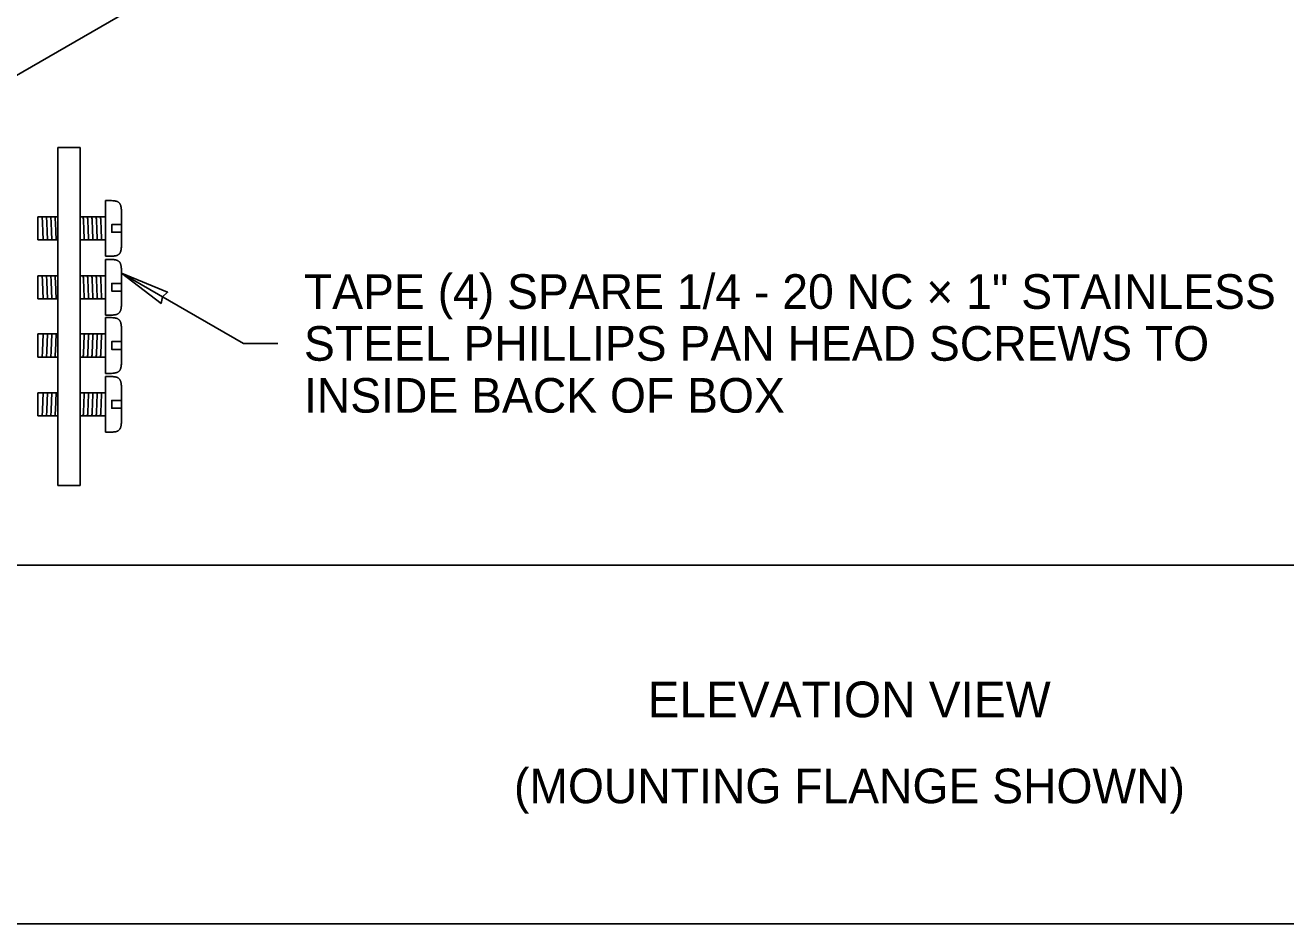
# Model space of a CAD drawing. Extents: x 99862 to 104211, y 98939 to 102076.
# Drawn here: x 100754 to 101337, y 100000 to 100415 of the extents above; entities that cross this region are included whole.
import ezdxf

# ---------------------------------------------------------------- set-up
doc = ezdxf.new("R2010")
doc.units = 0
for name, color, linetype in [('Level 1', 7, 'Continuous'), ('Level 15', 7, 'Continuous'), ('Level 20', 7, 'Continuous'), ('Level 3', 7, 'Continuous'), ('Level 4', 7, 'Continuous')]:
    doc.layers.add(name, color=color, linetype=linetype)

msp = doc.modelspace()

# ---------------------------------------------------------------- linework, layer by layer
at = {"layer": 'Level 1'}
for p, q in [((100768.9, 100202.13), (100768.9, 100358.41)), ((100768.9, 100358.41), (100779.31, 100358.41)), ((100779.31, 100358.41), (100779.31, 100202.13)), ((100779.31, 100202.13), (100768.9, 100202.13)), ((100779.31, 100202.13), (100779.31, 100202.13)), ((101689.83, 100165.23), (100609.83, 100165.23))]:
    msp.add_line(p, q, dxfattribs=at)
msp.add_lwpolyline([(99862, 99999.5), (103151, 99999.5), (103151, 102075.5), (99862, 102075.5)], close=True, dxfattribs=at)
at = {"layer": 'Level 15'}
for p, q in [((100587.71, 100298.08), (100839.76, 100443.6)), ((100798.43, 100300.26), (100854.72, 100267.76)), ((100854.72, 100267.76), (100870.72, 100267.76))]:
    msp.add_line(p, q, dxfattribs=at)
msp.add_lwpolyline([(100798.44, 100300.26), (100816.71, 100286.26), (100817.29, 100289.37), (100819.7, 100291.43)], close=True, dxfattribs=at)
at = {"layer": 'Level 3'}
for p, q in [((100790.94, 100308.03), (100790.94, 100333.82)), ((100768.9, 100326.27), (100759.66, 100326.27)), ((100759.66, 100326.27), (100759.66, 100315.59)), ((100790.94, 100326.27), (100779.42, 100326.27)), ((100798.44, 100327.47), (100798.44, 100314.39)), ((100759.66, 100315.59), (100768.9, 100315.59)), ((100790.94, 100315.59), (100779.42, 100315.59)), ((100790.94, 100280.82), (100790.94, 100306.61)), ((100768.9, 100299.06), (100759.66, 100299.06)), ((100759.66, 100299.06), (100759.66, 100288.38)), ((100790.94, 100299.06), (100779.42, 100299.06)), ((100798.44, 100300.26), (100798.44, 100287.18)), ((100759.66, 100288.38), (100768.9, 100288.38)), ((100779.42, 100288.38), (100790.94, 100288.38)), ((100790.94, 100253.92), (100790.94, 100279.71)), ((100768.9, 100272.16), (100759.66, 100272.16)), ((100759.66, 100272.16), (100759.66, 100261.48)), ((100779.42, 100272.16), (100790.94, 100272.16)), ((100798.44, 100273.36), (100798.44, 100260.28)), ((100759.66, 100261.48), (100768.9, 100261.48)), ((100790.94, 100261.48), (100779.42, 100261.48)), ((100790.94, 100226.72), (100790.94, 100252.51)), ((100768.9, 100244.95), (100759.66, 100244.95)), ((100759.66, 100244.95), (100759.66, 100234.27)), ((100790.94, 100244.95), (100779.42, 100244.95)), ((100798.44, 100246.15), (100798.44, 100233.07)), ((100759.66, 100234.27), (100768.9, 100234.27)), ((100790.94, 100234.27), (100779.42, 100234.27))]:
    msp.add_line(p, q, dxfattribs=at)
for points in [[(100798.44, 100322.7), (100793.89, 100322.7), (100793.89, 100319.15), (100798.44, 100319.15)], [(100798.44, 100295.49), (100793.89, 100295.49), (100793.89, 100291.95), (100798.44, 100291.95)], [(100798.44, 100268.59), (100793.89, 100268.59), (100793.89, 100265.04), (100798.44, 100265.04)], [(100798.44, 100241.39), (100793.89, 100241.39), (100793.89, 100237.84), (100798.44, 100237.84)]]:
    msp.add_lwpolyline(points, close=True, dxfattribs=at)
for points in [[(100790.94, 100333.82), (100791.15, 100333.82), (100792.36, 100333.82), (100793.72, 100333.82), (100794.98, 100333.7), (100795.36, 100333.64), (100795.71, 100333.57), (100796.03, 100333.49), (100796.33, 100333.39), (100796.61, 100333.27), (100796.86, 100333.13), (100797.17, 100332.91), (100797.44, 100332.64), (100797.66, 100332.32), (100797.81, 100332.03), (100797.94, 100331.69), (100798.05, 100331.3), (100798.15, 100330.84), (100798.23, 100330.3), (100798.3, 100329.69), (100798.38, 100328.74), (100798.42, 100327.99), (100798.44, 100327.47)], [(100798.44, 100314.39), (100798.42, 100313.87), (100798.38, 100313.12), (100798.3, 100312.16), (100798.23, 100311.55), (100798.15, 100311.02), (100798.05, 100310.56), (100797.94, 100310.17), (100797.81, 100309.83), (100797.66, 100309.54), (100797.44, 100309.22), (100797.17, 100308.95), (100796.86, 100308.73), (100796.61, 100308.59), (100796.33, 100308.47), (100796.03, 100308.37), (100795.71, 100308.28), (100795.36, 100308.22), (100794.98, 100308.16), (100793.72, 100308.03), (100792.36, 100308.04), (100791.15, 100308.03), (100790.94, 100308.03)], [(100790.94, 100306.61), (100791.15, 100306.62), (100792.36, 100306.61), (100793.72, 100306.62), (100794.98, 100306.49), (100795.36, 100306.43), (100795.71, 100306.36), (100796.03, 100306.28), (100796.33, 100306.18), (100796.61, 100306.06), (100796.86, 100305.92), (100797.17, 100305.7), (100797.44, 100305.43), (100797.66, 100305.11), (100797.81, 100304.82), (100797.94, 100304.48), (100798.05, 100304.09), (100798.15, 100303.63), (100798.23, 100303.1), (100798.3, 100302.48), (100798.38, 100301.53), (100798.42, 100300.78), (100798.44, 100300.26)], [(100798.44, 100287.18), (100798.42, 100286.66), (100798.38, 100285.91), (100798.3, 100284.96), (100798.23, 100284.34), (100798.15, 100283.81), (100798.05, 100283.35), (100797.94, 100282.96), (100797.81, 100282.62), (100797.66, 100282.33), (100797.44, 100282.01), (100797.17, 100281.74), (100796.86, 100281.52), (100796.61, 100281.38), (100796.33, 100281.26), (100796.03, 100281.16), (100795.71, 100281.08), (100795.36, 100281.01), (100794.98, 100280.95), (100793.72, 100280.82), (100792.36, 100280.83), (100791.15, 100280.82), (100790.94, 100280.82)], [(100790.94, 100279.71), (100791.15, 100279.71), (100792.36, 100279.71), (100793.72, 100279.71), (100794.98, 100279.59), (100795.36, 100279.53), (100795.71, 100279.46), (100796.03, 100279.38), (100796.33, 100279.28), (100796.61, 100279.16), (100796.86, 100279.02), (100797.17, 100278.8), (100797.44, 100278.53), (100797.66, 100278.21), (100797.81, 100277.92), (100797.94, 100277.58), (100798.05, 100277.19), (100798.15, 100276.73), (100798.23, 100276.2), (100798.3, 100275.58), (100798.38, 100274.63), (100798.42, 100273.88), (100798.44, 100273.36)], [(100798.44, 100260.28), (100798.42, 100259.76), (100798.38, 100259.01), (100798.3, 100258.06), (100798.23, 100257.44), (100798.15, 100256.91), (100798.05, 100256.45), (100797.94, 100256.06), (100797.81, 100255.72), (100797.66, 100255.43), (100797.44, 100255.11), (100797.17, 100254.84), (100796.86, 100254.62), (100796.61, 100254.48), (100796.33, 100254.36), (100796.03, 100254.26), (100795.71, 100254.18), (100795.36, 100254.11), (100794.98, 100254.05), (100793.72, 100253.92), (100792.36, 100253.93), (100791.15, 100253.92), (100790.94, 100253.92)], [(100790.94, 100252.51), (100791.15, 100252.51), (100792.36, 100252.5), (100793.72, 100252.51), (100794.98, 100252.38), (100795.36, 100252.32), (100795.71, 100252.25), (100796.03, 100252.17), (100796.33, 100252.07), (100796.61, 100251.95), (100796.86, 100251.81), (100797.17, 100251.59), (100797.44, 100251.32), (100797.66, 100251), (100797.81, 100250.71), (100797.94, 100250.37), (100798.05, 100249.98), (100798.15, 100249.52), (100798.23, 100248.99), (100798.3, 100248.37), (100798.38, 100247.42), (100798.42, 100246.67), (100798.44, 100246.15)], [(100798.44, 100233.07), (100798.42, 100232.55), (100798.38, 100231.8), (100798.3, 100230.85), (100798.23, 100230.23), (100798.15, 100229.7), (100798.05, 100229.24), (100797.94, 100228.85), (100797.81, 100228.51), (100797.66, 100228.22), (100797.44, 100227.9), (100797.17, 100227.63), (100796.86, 100227.41), (100796.61, 100227.27), (100796.33, 100227.15), (100796.03, 100227.05), (100795.71, 100226.97), (100795.36, 100226.9), (100794.98, 100226.84), (100793.72, 100226.72), (100792.36, 100226.72), (100791.15, 100226.72), (100790.94, 100226.72)]]:
    msp.add_open_spline(points, degree=3, dxfattribs=at)
at = {"layer": 'Level 4'}
for points in [[(100761.94, 100320.93), (100761.88, 100322.52), (100761.78, 100324.99), (100761.68, 100326.09), (100761.64, 100326.27)], [(100763.64, 100326.27), (100763.68, 100326.09), (100763.78, 100324.99), (100763.88, 100322.52), (100763.94, 100320.93)], [(100765.94, 100320.93), (100765.88, 100322.52), (100765.78, 100324.99), (100765.68, 100326.09), (100765.64, 100326.27)], [(100767.64, 100326.27), (100767.68, 100326.09), (100767.78, 100324.99), (100767.88, 100322.52), (100767.94, 100320.93)], [(100780.64, 100326.27), (100780.68, 100326.09), (100780.78, 100324.99), (100780.88, 100322.52), (100780.94, 100320.93)], [(100782.64, 100326.27), (100782.68, 100326.09), (100782.78, 100324.99), (100782.88, 100322.52), (100782.94, 100320.93)], [(100784.64, 100326.27), (100784.68, 100326.09), (100784.78, 100324.99), (100784.88, 100322.52), (100784.94, 100320.93)], [(100786.64, 100326.27), (100786.68, 100326.09), (100786.78, 100324.99), (100786.88, 100322.52), (100786.94, 100320.93)], [(100788.64, 100326.27), (100788.68, 100326.09), (100788.78, 100324.99), (100788.88, 100322.52), (100788.94, 100320.93)], [(100762.25, 100315.59), (100762.21, 100315.77), (100762.11, 100316.86), (100762.01, 100319.33), (100761.94, 100320.93)], [(100763.94, 100320.93), (100764.01, 100319.33), (100764.11, 100316.86), (100764.21, 100315.77), (100764.25, 100315.59)], [(100766.25, 100315.59), (100766.21, 100315.77), (100766.11, 100316.86), (100766.01, 100319.33), (100765.94, 100320.93)], [(100767.94, 100320.93), (100768.01, 100319.33), (100768.11, 100316.86), (100768.21, 100315.77), (100768.25, 100315.59)], [(100780.94, 100320.93), (100781.01, 100319.33), (100781.11, 100316.86), (100781.21, 100315.77), (100781.25, 100315.59)], [(100782.94, 100320.93), (100783.01, 100319.33), (100783.11, 100316.86), (100783.21, 100315.77), (100783.25, 100315.59)], [(100784.94, 100320.93), (100785.01, 100319.33), (100785.11, 100316.86), (100785.21, 100315.77), (100785.25, 100315.59)], [(100786.94, 100320.93), (100787.01, 100319.33), (100787.11, 100316.86), (100787.21, 100315.77), (100787.25, 100315.59)], [(100788.94, 100320.93), (100789.01, 100319.33), (100789.11, 100316.86), (100789.21, 100315.77), (100789.25, 100315.59)], [(100761.94, 100293.72), (100761.88, 100295.31), (100761.78, 100297.78), (100761.68, 100298.88), (100761.64, 100299.06)], [(100763.64, 100299.06), (100763.68, 100298.88), (100763.78, 100297.78), (100763.88, 100295.31), (100763.94, 100293.72)], [(100765.94, 100293.72), (100765.88, 100295.31), (100765.78, 100297.78), (100765.68, 100298.88), (100765.64, 100299.06)], [(100767.64, 100299.06), (100767.68, 100298.88), (100767.78, 100297.78), (100767.88, 100295.31), (100767.94, 100293.72)], [(100780.64, 100299.06), (100780.68, 100298.88), (100780.78, 100297.78), (100780.88, 100295.31), (100780.94, 100293.72)], [(100782.94, 100293.72), (100782.88, 100295.31), (100782.78, 100297.78), (100782.68, 100298.88), (100782.64, 100299.06)], [(100784.64, 100299.06), (100784.68, 100298.88), (100784.78, 100297.78), (100784.88, 100295.31), (100784.94, 100293.72)], [(100786.94, 100293.72), (100786.88, 100295.31), (100786.78, 100297.78), (100786.68, 100298.88), (100786.64, 100299.06)], [(100788.64, 100299.06), (100788.68, 100298.88), (100788.78, 100297.78), (100788.88, 100295.31), (100788.94, 100293.72)], [(100762.25, 100288.38), (100762.21, 100288.56), (100762.11, 100289.66), (100762.01, 100292.12), (100761.94, 100293.72)], [(100763.94, 100293.72), (100764.01, 100292.12), (100764.11, 100289.66), (100764.21, 100288.56), (100764.25, 100288.38)], [(100766.25, 100288.38), (100766.21, 100288.56), (100766.11, 100289.66), (100766.01, 100292.12), (100765.94, 100293.72)], [(100767.94, 100293.72), (100768.01, 100292.12), (100768.11, 100289.66), (100768.21, 100288.56), (100768.25, 100288.38)], [(100780.94, 100293.72), (100781.01, 100292.12), (100781.11, 100289.66), (100781.21, 100288.56), (100781.25, 100288.38)], [(100783.25, 100288.38), (100783.21, 100288.56), (100783.11, 100289.66), (100783.01, 100292.12), (100782.94, 100293.72)], [(100784.94, 100293.72), (100785.01, 100292.12), (100785.11, 100289.66), (100785.21, 100288.56), (100785.25, 100288.38)], [(100787.25, 100288.38), (100787.21, 100288.56), (100787.11, 100289.66), (100787.01, 100292.12), (100786.94, 100293.72)], [(100788.94, 100293.72), (100789.01, 100292.12), (100789.11, 100289.66), (100789.21, 100288.56), (100789.25, 100288.38)], [(100762.25, 100272.16), (100762.21, 100271.98), (100762.11, 100270.88), (100762.01, 100268.41), (100761.94, 100266.82)], [(100763.94, 100266.82), (100764.01, 100268.41), (100764.11, 100270.88), (100764.21, 100271.98), (100764.25, 100272.16)], [(100766.25, 100272.16), (100766.21, 100271.98), (100766.11, 100270.88), (100766.01, 100268.41), (100765.94, 100266.82)], [(100768.25, 100272.16), (100768.21, 100271.98), (100768.11, 100270.88), (100768.01, 100268.41), (100767.94, 100266.82)], [(100781.25, 100272.16), (100781.21, 100271.98), (100781.11, 100270.88), (100781.01, 100268.41), (100780.94, 100266.82)], [(100782.94, 100266.82), (100783.01, 100268.41), (100783.11, 100270.88), (100783.21, 100271.98), (100783.25, 100272.16)], [(100785.25, 100272.16), (100785.21, 100271.98), (100785.11, 100270.88), (100785.01, 100268.41), (100784.94, 100266.82)], [(100786.94, 100266.82), (100787.01, 100268.41), (100787.11, 100270.88), (100787.21, 100271.98), (100787.25, 100272.16)], [(100789.25, 100272.16), (100789.21, 100271.98), (100789.11, 100270.88), (100789.01, 100268.41), (100788.94, 100266.82)], [(100761.94, 100266.82), (100761.88, 100265.22), (100761.78, 100262.76), (100761.68, 100261.66), (100761.64, 100261.48)], [(100763.64, 100261.48), (100763.68, 100261.66), (100763.78, 100262.76), (100763.88, 100265.22), (100763.94, 100266.82)], [(100765.94, 100266.82), (100765.88, 100265.22), (100765.78, 100262.76), (100765.68, 100261.66), (100765.64, 100261.48)], [(100767.94, 100266.82), (100767.88, 100265.22), (100767.78, 100262.76), (100767.68, 100261.66), (100767.64, 100261.48)], [(100780.94, 100266.82), (100780.88, 100265.22), (100780.78, 100262.76), (100780.68, 100261.66), (100780.64, 100261.48)], [(100782.64, 100261.48), (100782.68, 100261.66), (100782.78, 100262.76), (100782.88, 100265.22), (100782.94, 100266.82)], [(100784.94, 100266.82), (100784.88, 100265.22), (100784.78, 100262.76), (100784.68, 100261.66), (100784.64, 100261.48)], [(100786.64, 100261.48), (100786.68, 100261.66), (100786.78, 100262.76), (100786.88, 100265.22), (100786.94, 100266.82)], [(100788.94, 100266.82), (100788.88, 100265.22), (100788.78, 100262.76), (100788.68, 100261.66), (100788.64, 100261.48)], [(100762.25, 100244.95), (100762.21, 100244.77), (100762.11, 100243.67), (100762.01, 100241.21), (100761.94, 100239.61)], [(100763.94, 100239.61), (100764.01, 100241.21), (100764.11, 100243.67), (100764.21, 100244.77), (100764.25, 100244.95)], [(100766.25, 100244.95), (100766.21, 100244.77), (100766.11, 100243.67), (100766.01, 100241.21), (100765.94, 100239.61)], [(100767.94, 100239.61), (100768.01, 100241.21), (100768.11, 100243.67), (100768.21, 100244.77), (100768.25, 100244.95)], [(100780.94, 100239.61), (100781.01, 100241.21), (100781.11, 100243.67), (100781.21, 100244.77), (100781.25, 100244.95)], [(100783.25, 100244.95), (100783.21, 100244.77), (100783.11, 100243.67), (100783.01, 100241.21), (100782.94, 100239.61)], [(100784.94, 100239.61), (100785.01, 100241.21), (100785.11, 100243.67), (100785.21, 100244.77), (100785.25, 100244.95)], [(100787.25, 100244.95), (100787.21, 100244.77), (100787.11, 100243.67), (100787.01, 100241.21), (100786.94, 100239.61)], [(100788.94, 100239.61), (100789.01, 100241.21), (100789.11, 100243.67), (100789.21, 100244.77), (100789.25, 100244.95)], [(100761.94, 100239.61), (100761.88, 100238.02), (100761.78, 100235.55), (100761.68, 100234.45), (100761.64, 100234.27)], [(100763.64, 100234.27), (100763.68, 100234.45), (100763.78, 100235.55), (100763.88, 100238.02), (100763.94, 100239.61)], [(100765.94, 100239.61), (100765.88, 100238.02), (100765.78, 100235.55), (100765.68, 100234.45), (100765.64, 100234.27)], [(100767.64, 100234.27), (100767.68, 100234.45), (100767.78, 100235.55), (100767.88, 100238.02), (100767.94, 100239.61)], [(100780.64, 100234.27), (100780.68, 100234.45), (100780.78, 100235.55), (100780.88, 100238.02), (100780.94, 100239.61)], [(100782.94, 100239.61), (100782.88, 100238.02), (100782.78, 100235.55), (100782.68, 100234.45), (100782.64, 100234.27)], [(100784.64, 100234.27), (100784.68, 100234.45), (100784.78, 100235.55), (100784.88, 100238.02), (100784.94, 100239.61)], [(100786.94, 100239.61), (100786.88, 100238.02), (100786.78, 100235.55), (100786.68, 100234.45), (100786.64, 100234.27)], [(100788.64, 100234.27), (100788.68, 100234.45), (100788.78, 100235.55), (100788.88, 100238.02), (100788.94, 100239.61)]]:
    msp.add_open_spline(points, degree=3, dxfattribs=at)

# ---------------------------------------------------------------- texts
at = {"layer": 'Level 20'}
for s, height, p in [('TAPE (4) SPARE 1/4 - 20 NC × 1" STAINLESS', 16, (100882.72, 100283.76)), ('STEEL PHILLIPS PAN HEAD SCREWS TO ', 16, (100882.72, 100259.76)), ('INSIDE BACK OF BOX', 16, (100882.72, 100235.76)), ('ELEVATION VIEW', 16.5, (101041.63, 100094.97)), ('(MOUNTING FLANGE SHOWN)', 16, (100979.82, 100055.22))]:
    msp.add_text(s, height=height, dxfattribs=at).set_placement(p)

doc.saveas('drawing.dxf')
